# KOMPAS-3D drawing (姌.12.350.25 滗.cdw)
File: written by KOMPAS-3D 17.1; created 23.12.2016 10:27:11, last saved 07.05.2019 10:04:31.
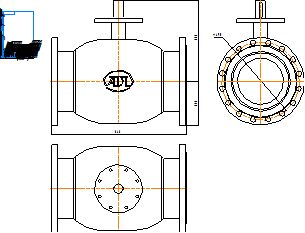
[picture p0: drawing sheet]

Sheet 1: A4, portrait

Title block, sheet 1: name: КШ.12.350.25 фф; material: Внимание! Данный продукт является объектом авторского права ООО «Торговый Дом АДЛ». / Запрещается изменение, копирование, распространение / (в том числе путем копирования на другие сайты и ресурсы в Интернете) / или любое иное использование информации и объектов без предварительного / согласия правообладателя (ООО «Торговый Дом АДЛ»).; sheets: 1; organisation: ООО "Торговый дом АДЛ"; sheet format: A4; stored path: C:\Users\tra\Desktop\2д чертежи\Шаровые краны БИВАЛ\КШ_Бивал_серия_11_12\KOMPAS_2D\КШ.12.350.25 фф.cdw

Views: Вид 1, Проекционный вид 2, Проекционный вид 3
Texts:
  Klimkovich
  ADL
Dimensions and other numbers on the sheet: 848; 275; 505; 490; 1:1; 1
